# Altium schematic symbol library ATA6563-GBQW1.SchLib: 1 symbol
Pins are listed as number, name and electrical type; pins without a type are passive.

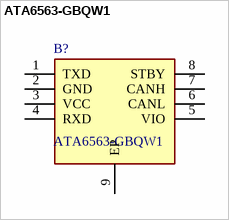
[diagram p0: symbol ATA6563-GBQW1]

## ATA6563-GBQW1
designator B?
CAN Interface IC CAN TRX with VIO PIN (DFN8); Manufacturer_Name: Microchip; Geometry.Height: 0.9mm
footprint SON65P300X300X90-9N-D
pins: 1 TXD, 2 GND, 3 VCC, 4 RXD, 5 VIO, 6 CANL, 7 CANH, 8 STBY, 9 EP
